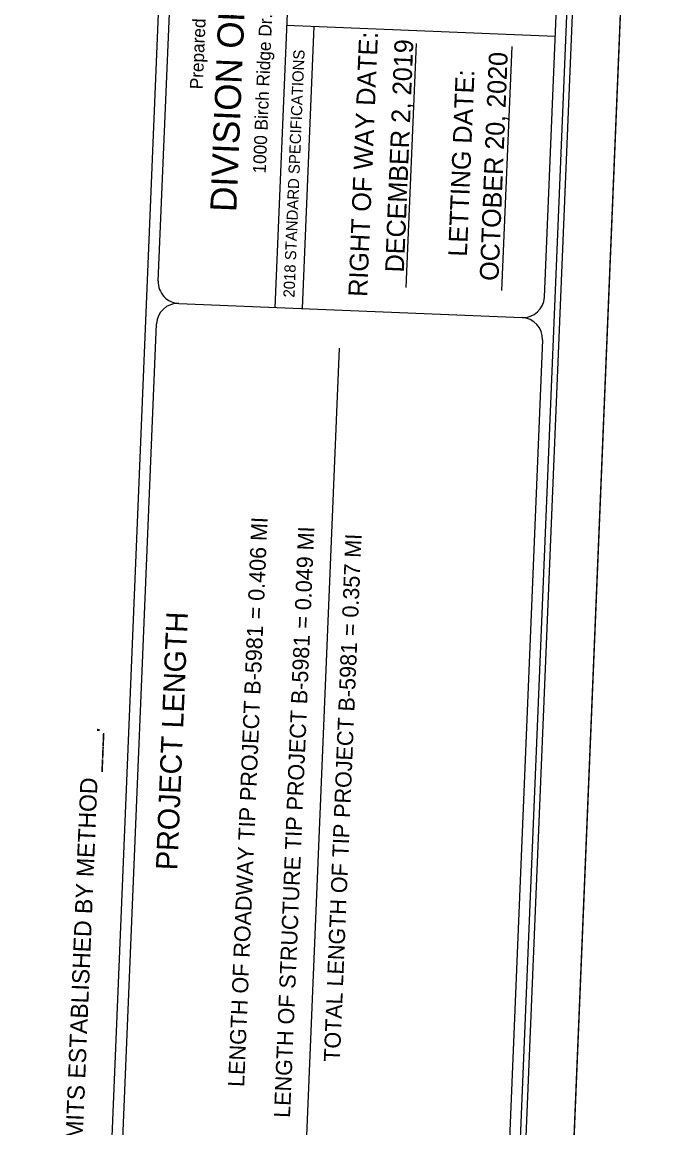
# Model space of a CAD drawing. Extents: x 2264506 to 2267635, y 507918 to 512596.
# Drawn here: x 2266878 to 2267635, y 509740 to 511027 of the extents above; entities that cross this region are included whole.
import ezdxf

# ---------------------------------------------------------------- set-up
doc = ezdxf.new("R2010")
doc.units = 0
for name, color, linetype in [('Default', 7, 'Continuous'), ('Matchline', 7, 'Continuous'), ('Prop Horizontal Alignment', 7, 'Continuous'), ('Prop Horizontal Alignment Station Label', 7, 'Continuous'), ('Prop Horizontal Alignment Tick Label', 7, 'Continuous'), ('Prop Horizontal Alignment Tick Large', 7, 'Continuous'), ('Prop Structure Anchor Unit CELL', 7, 'Continuous')]:
    doc.layers.add(name, color=color, linetype=linetype)

msp = doc.modelspace()

# ---------------------------------------------------------------- linework, layer by layer
at = {"layer": 'Default'}
msp.add_line((2267209, 509711.5), (2267247.7, 510647.5), dxfattribs=at)
at = {"layer": 'Matchline'}
msp.add_line((2267446.4, 507917.5), (2267620.2, 512123.9), dxfattribs=at)
at = {"layer": 'Prop Horizontal Alignment Station Label'}
for p, q in [((2266948.1, 508877.5), (2267094.6, 512424.5)), ((2267204.2, 511456.7), (2267172.7, 510694.8)), ((2267036.9, 510725.5), (2267066.3, 511437.3)), ((2267186.2, 511023.4), (2267499.1, 511010.5)), ((2267218.1, 511022.1), (2267204.5, 510693.5)), ((2267337, 511002.2), (2267325.3, 510718)), ((2267448.4, 510998.6), (2267436.7, 510714.4)), ((2267214.2, 510927.4), (2267214.2, 510927.4)), ((2267331.1, 510860), (2267331.1, 510860)), ((2267060.9, 510699.4), (2267460.5, 510682.9)), ((2266995.7, 509726.3), (2267034.9, 510675.5))]:
    msp.add_line(p, q, dxfattribs=at)
for points in [[(2267417, 508720.6), (2267569.8, 512417.4)], [(2267486.6, 510706.9), (2267516, 511418.8)], [(2267445.3, 509707.7), (2267484.5, 510656.9)]]:
    msp.add_lwpolyline(points, dxfattribs=at)
for centre, start, end in [((2267061.8, 510724.4), 177.6342, 267.6342), ((2267059.7, 510674.5), 87.6342, 177.6342), ((2267461.5, 510707.9), 267.6342, 357.6342), ((2267459.4, 510658), 357.6342, 87.6342)]:
    msp.add_arc(centre, 25, start, end, dxfattribs=at)
at = {"layer": 'Prop Horizontal Alignment Tick Label'}
msp.add_lwpolyline([(2267406.5, 508310.6), (2267578.5, 512473.3), (2264943, 512582.2), (2264771, 508419.5)], close=True, dxfattribs=at)
at = {"layer": 'Prop Horizontal Alignment Tick Large'}
msp.add_lwpolyline([(2264887.3, 512595.8), (2264713.6, 508389.4), (2267461.2, 508275.9), (2267635, 512482.3)], close=True, dxfattribs=at)

# ---------------------------------------------------------------- texts
at = {"layer": 'Default'}
for s, p in [('LENGTH OF ROADWAY TIP PROJECT B-5981 = 0.406 MI', (2267136.8, 509787)), ('LENGTH OF STRUCTURE TIP PROJECT B-5981 = 0.049 MI', (2267190.2, 509751)), ('TOTAL LENGTH OF TIP PROJECT B-5981 = 0.357 MI', (2267248.3, 509816.2))]:
    msp.add_text(s, height=18.75, rotation=87.6342, dxfattribs=at).set_placement(p)
at = {"layer": 'Prop Horizontal Alignment'}
for s, p in [('DECEMBER 2, 2019', (2267322.8, 510735.2)), ('OCTOBER 20, 2020', (2267432.9, 510725.3))]:
    msp.add_text(s, height=21.875, rotation=87.6342, dxfattribs=at).set_placement(p)
at = {"layer": 'Prop Horizontal Alignment Station Label'}
for s, height, p in [('DIVISION OF HIGHWAYS', 30.468, (2267127.7, 510805.5)), ('1000 Birch Ridge Dr., Raleigh, NC 27610', 15, (2267161.9, 510850.4)), ('Prepared in the Office of:', 14.998, (2267088.6, 510948.5)), ('RIGHT OF WAY DATE: ', 21.874, (2267280, 510706.8)), ('2018 STANDARD SPECIFICATIONS', 13, (2267195.4, 510706)), ('LETTING DATE:', 21.874, (2267396.2, 510753.6)), ('PROJECT LENGTH', 24.999, (2267059, 510039.2))]:
    msp.add_text(s, height=height, rotation=87.6342, dxfattribs=at).set_placement(p)
at = {"layer": 'Prop Structure Anchor Unit CELL'}
msp.add_text('CLEARING ON THIS PROJECT SHALL BE PERFORMED TO THE LIMITS ESTABLISHED BY METHOD ___.', height=20, rotation=87.6342, dxfattribs=at).set_placement((2266914.4, 508892.4))

doc.saveas('drawing.dxf')
